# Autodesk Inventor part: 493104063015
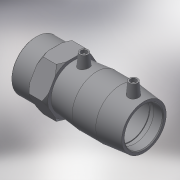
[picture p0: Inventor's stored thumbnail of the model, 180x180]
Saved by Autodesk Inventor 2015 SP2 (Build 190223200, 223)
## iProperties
Created: 2017-06
Part Number: 493104063015
Material: Generic
Description: PLASSON FEMALE TRANSITION COUPLER 63-1.1/2"
Document SubType Name: Modeling
Designer: KIM
Mass: 444.523 g
Surface Area: 714.486 cm^2
Volume: 444.523 cm^3
Density: 1 g/cm^3
Appearance: Default
Author: KIM
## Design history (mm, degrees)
derived "493104.ipt"
feature "Solid1::493104.ipt"
tag "TaggingFeature1"
body "Solid1"
other parameters: "d0" = 119, "d1" = 63, "d2" = 82, "d3" = 59, "d4" = 39.66667, "d5" = 73.8, "d6" = 59.85, "d7" = 63, "d8" = 168 deg, "d10" = 23.6, "d11" = 7.86667, "d29" = 59, "d30" = 14, "d31" = 41.65, "d34" = 5 deg, "d41" = 4, "d42" = 14, "d43" = 0, "d48" = 3, "d49" = 0, "d55" = 26, "d57" = 38, "d59" = 44.845, "d60" = 23.4, "d70" = 82, "d71" = 13, "d72" = 0, "d73" = 45 deg, "d74" = 3.8, "d75" = 45 deg, "d77" = 0.945, "d80" = 1.26, "d_" = 63, "L_" = 145, "L_1" = 59, "D_1" = 82, "A_" = 59, "d_2" = 12, "L_2" = 26, "D_" = 38, "R_p" = 44.845
